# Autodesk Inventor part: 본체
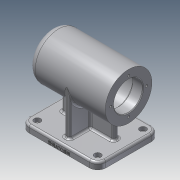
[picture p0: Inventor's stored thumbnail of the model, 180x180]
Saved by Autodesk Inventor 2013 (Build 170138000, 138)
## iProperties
Created: 2020-10
Part Number: 본체
Material: 알루미늄 6061
Document SubType Name: Modeling
Designer: user
Density: 2.71 g/cm^3
Mass: 1030.08 g
Surface Area: 757.984 cm^2
Volume: 380.102 cm^3
Author: user
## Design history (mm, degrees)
sketch "스케치1"
  geometry: C1 r 34 at (0, 0); 1 further point
  constraints: 1 centre point, 1 coincident
  dimensions: "d0" = 68 diameter of C1
extrude "돌출1" new body sketch "스케치1" stored distance "d1" = 112; taper "d2" = 0 deg
sketch "스케치2"
  geometry: L1 (34, -56)-(-34, -56) reference; L2 (-34, -56)-(-34, 56) reference; L3 (-34, 56)-(34, 56) reference; L4 (34, 56)-(34, -56) reference; L5 (0, -56)-(21, -56); L6 (21, -56)-(21, -41); L7 (21, -41)-(24, -41); L8 (24, -41)-(24, 13); L9 (24, 13)-(21, 13); L10 (21, 13)-(21, 25); L11 (21, 25)-(17.5, 25); L12 (17.5, 25)-(17.5, 43); L13 (17.5, 43)-(16, 43); L14 (16, 43)-(16, 47); L15 (16, 47)-(10.5, 47); L16 (10.5, 47)-(10.5, 50); L17 (10.5, 50)-(0, 50); L18 (0, 50)-(0, -56); 1 further point
  constraints: 28 end point, 7 parallel, 5 perpendicular, 1 collinear, 1 midpoint, 1 point on line
  dimensions: "d3" = 3 distance of L15.end L16.end; "d5" = 4 distance of L13.end L14.end; "d6" = 18 distance of L11.end L12.end; "d7" = 12 distance of L9.end L10.end; "d8" = 54 distance of L7.end L8.end; "d9" = 15 distance of L5.end L6.end; "d10" = 42 diameter of L6 L18; "d11" = 48 diameter of L8 L18; "d12" = 42 diameter of L10 L18; "d13" = 21 diameter of L16 L18; "d14" = 32 diameter of L14 L18; "d15" = 35 diameter of L12 L18
revolve "회전1" sketch "스케치2" stored, may be unused: angle "d16" = 90 deg
sketch "스케치3" dims "d17" = 52
  geometry: C1 r 21 at (0, 0) reference; C2 r 34 at (0, 0) reference; 2 further points
  constraints: 2 vertical alignment, 1 coincident, 2 other
hole "구멍1" sketch "스케치3" at (0, 26) diameter "d18" = 3.242; stored, may be unused: countersink angle "d22" = 90 deg, drill point angle "d24" = 118 deg; dims "d19" = 8, "d20" = 4, "d21" = 2, "d23" = 11
node "작업 평면1"
sketch "스케치4"
  geometry: L1 (34, -56)-(34, 56) reference; L2 (34, 56)-(-34, 56) reference; L3 (-34, -56)-(34, -56) reference; L4 (-34, -56)-(-34, 56) reference; L5 (-45, 56)-(45, 56); L6 (45, 56)-(45, -56); L7 (45, -56)-(-45, -56); L8 (-45, -56)-(-45, 56); L9 (-45, 56)-(45, -56); L10 (45, 56)-(-45, -56); 1 further point
  constraints: 12 end point, 2 midpoint, 2 parallel, 1 horizontal, 1 perpendicular
  dimensions: "d29" = 90 distance of L6.end L7.end; "d30" = 112 distance of L5.end L6.end
extrude "돌출2" join sketch "스케치4" distance "d31" = 10; taper "d32" = 0 deg
sketch "스케치5"
  geometry: L1 (56, -45)-(56, 45) reference; L2 (-56, 45)-(-56, -45) reference; L3 (-38, -4)-(38, -4); L4 (38, -4)-(38, 4); L5 (38, 4)-(-38, 4); L6 (-38, 4)-(-38, -4); 2 further points
  constraints: 8 end point, 2 parallel, 1 horizontal, 1 horizontal alignment, 1 midpoint, 1 perpendicular
  dimensions: "d33" = 8 distance of L3.end L4.end; "d35" = 18 distance between parallel lines of L6 L2; "d36" = 18 distance between parallel lines of L1 L4
extrude "돌출3" join sketch "스케치5" stored distance "d37" = 10; taper "d38" = 0 deg
sketch "스케치6"
  geometry: L1 (64, 45)-(74, 45) reference; L2 (74, 45)-(74, -45) reference; L3 (74, -45)-(64, -45) reference; L4 (64, -45)-(64, -4) reference; L5 (64, -4)-(33.764, -4) reference; L6 (33.764, 4)-(64, 4) reference; L7 (64, 4)-(64, 45) reference; L8 (0, -34)-(64, -34); C1 r 24 at (0, 0) reference; A1 r 34 centre (0, 0) between (33.764, 4) and (33.764, -4) reference; 1 further point
  constraints: 2 end point, 1 perpendicular, 1 point on circle, 1 point on line, 1 tangent
feature "리브1" sketch "스케치6" dims "d39" = 1, "d40" = 8, "d41" = 0, "d42" = 0, "d43" = 1, "d44" = 1
fillet "모깎기1" dims "d45" = 12
sketch "스케치7"
  geometry: A1 r 12 centre (44, -33) between (44, -45) and (56, -33) reference; A2 r 12 centre (44, 33) between (56, 33) and (44, 45) reference; A3 r 12 centre (-44, 33) between (-44, 45) and (-56, 33) reference; A4 r 12 centre (-44, -33) between (-56, -33) and (-44, -45) reference; 5 further points
  constraints: 4 coincident
hole "구멍2" sketch "스케치7" at (-44, 33), (44, 33), (44, -33), (-44, -33) diameter "d46" = 5.5; stored, may be unused: countersink angle "d50" = 90 deg, drill point angle "d52" = 118 deg; dims "d47" = 5.5, "d48" = 9.5, "d49" = 5.4, "d51" = 11
fillet "모깎기2" dims "d53" = 10
sketch "스케치8"
  geometry: L1 (0, 100)-(-10, 100) reference; 3 further points
  constraints: 1 other
  dimensions: "d54" = 3 horizontal distance of point (0, 88) point (-3, 44); "d55" = 56 distance from line of L1 point (-3, 44)
feature "엠보싱1" sketch "스케치8" dims "d56" = 0.5, "d57" = 0
fillet "모깎기3" dims "d58" = 3
fillet "모깎기4" dims "d59" = 0.3
fillet "모깎기5" dims "d60" = 3
chamfer "모따기1" distance "d61" = 1; stored, may be unused: second distance "d62" = 2, angle "d63" = 45 deg
fillet "모깎기6" dims "d64" = 3
fillet "모깎기7" dims "d65" = 3
fillet "모깎기8" dims "d66" = 3
fillet "모깎기9" dims "d67" = 3
fillet "모깎기10" dims "d68" = 3
node "솔리드1"
pattern_circular "원형 패턴1" dims angle "d26" = 360 deg
mirror "대칭1"
node "절단 모서리 투영1"
node "절단 모서리 투영2"
other parameters: "d28" = 74
